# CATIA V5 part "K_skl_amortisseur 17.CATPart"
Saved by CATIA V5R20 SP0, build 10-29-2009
Part number: skl_amortisseur 17
Publications: "longueur amortisseur", "longueur axe pivot", "liaison 10/17 sur 17", "droite appui verin gauche", "Droite.1", "Droite.3", "Plan.-55"
Bounding box of the stored display mesh (mm): x -55 to 95, y -775 to -396.053, z 128.478 to 285
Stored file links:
  G:\Khaled_CFAO_2011\SIL\SIL_GR2\mdardier\Khaled\CAD_ThinkMOTION\K_skl_amortisseur 17.CATPart
  G:\Khaled_CFAO_2011\SIL\SIL_GR2\mdardier\Khaled\CAD_ThinkMOTION\K_skl_ass_tandem.CATProduct
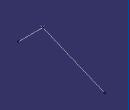
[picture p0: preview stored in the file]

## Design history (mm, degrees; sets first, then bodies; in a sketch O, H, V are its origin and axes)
External parameters (linked from other documents)
  `External.longueur amortisseur` = 410 mm
  `External.longueur axe pivot` = 150 mm
Set1
  Point1 "liaison 10/17 sur 17": linked copy from another document
  Line1 "droite appui verin gauche": linked copy from another document
  Plane1 "Plan.-55": linked copy from another document
Set2
  Line2: type PtDir, RefPoint Point1, Direction Line1, Start 0, End 410 {= `External.longueur amortisseur`}
  Line3: type Normal, RefPoint Point1, RefSkin Plane1, Start 0, End 150 {= `External.longueur axe pivot`}
Body1 (main body)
